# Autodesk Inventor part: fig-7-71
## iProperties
Shininess: 64.0
Length Units: 11269
Angle Units: 11279
Time Units: 11290
Mass Units: 11283
Length Display Precision: 3
Angle Display Precision: 2
Compacted: True
Part Number: fig-7-71
Document SubType Name: Modeling
Created: 2002-12
Designer: deepak
Density: 1 g/cm^3
Density: 0.0
Volumn: 0.0
Area: 0.0
PropertySet Name: Model Information
Control State: 0
Master: False
Checked Out: False
Author: deepak
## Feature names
1. Extrusion1
